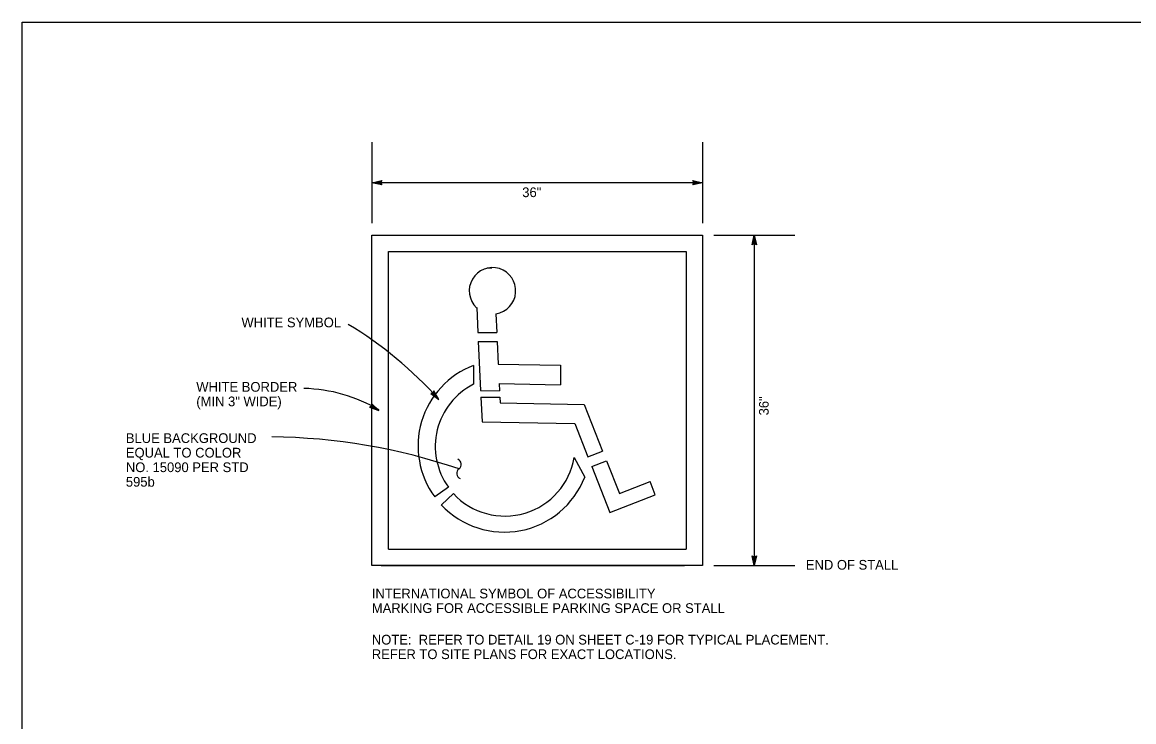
# Model space of a CAD drawing. Extents: x -121933 to -117742, y -103160 to -100084.
# Drawn here: x -119542 to -118856, y -101555 to -101122 of the extents above; entities that cross this region are included whole.
import ezdxf

# ---------------------------------------------------------------- set-up
doc = ezdxf.new("R2010")
doc.units = 0
for name, color, linetype in [('56 Stage 3 Anno', 7, 'Continuous'), ('57 Undefined', 7, 'Continuous'), ('60 Nongeo Data', 7, 'Continuous'), ('Default', 7, 'Continuous'), ('G-MARK', 7, 'Continuous'), ('G-TEXT', 7, 'Continuous'), ('Misc CnstDet(22)', 7, 'Continuous')]:
    doc.layers.add(name, color=color, linetype=linetype)

msp = doc.modelspace()

# ---------------------------------------------------------------- linework, layer by layer
at = {"layer": '56 Stage 3 Anno'}
for p, q in [((-119288.59, -101351.52), (-119290.12, -101351.82)), ((-119290.12, -101351.82), (-119290.12, -101351.82)), ((-119290.12, -101351.82), (-119285.13, -101355.41)), ((-119289.71, -101351.74), (-119286.05, -101354.38)), ((-119289.29, -101351.68), (-119286.97, -101353.34)), ((-119288.91, -101351.58), (-119287.89, -101352.31)), ((-119288.13, -101350.04), (-119288.59, -101351.52)), ((-119287.89, -101352.31), (-119288.49, -101351.23)), ((-119286.97, -101353.34), (-119288.38, -101350.82)), ((-119286.05, -101354.36), (-119288.24, -101350.46)), ((-119285.13, -101355.41), (-119288.13, -101350.04)), ((-119288.13, -101350.04), (-119288.13, -101350.04)), ((-119326.58, -101359.54), (-119327.95, -101360.28)), ((-119327.95, -101360.28), (-119327.95, -101360.28)), ((-119327.95, -101360.28), (-119322.1, -101362.18)), ((-119327.58, -101360.09), (-119323.29, -101361.48)), ((-119327.2, -101359.9), (-119324.48, -101360.78)), ((-119326.87, -101359.69), (-119325.67, -101360.07)), ((-119324.48, -101360.78), (-119326.6, -101358.8)), ((-119322.1, -101362.18), (-119326.59, -101357.98)), ((-119326.59, -101357.98), (-119326.59, -101357.98)), ((-119326.59, -101357.98), (-119326.58, -101359.54)), ((-119325.67, -101360.07), (-119326.58, -101359.23)), ((-119323.3, -101361.47), (-119326.57, -101358.41)), ((-119285.13, -101355.41), (-119285.13, -101355.41)), ((-119322.1, -101362.18), (-119322.1, -101362.18))]:
    msp.add_line(p, q, dxfattribs=at)
for centre, radius, start, end in [((-119466, -101516.62), 242.29, 41.71293, 58.95046), ((-119370.71, -101444.64), 96.01, 59.46122, 88.63427), ((-119391.38, -101745.24), 366.62, 71.09935, 89.52035), ((-119274.66, -101395.61), 3.45, 306.2821, 67.87649), ((-119270.58, -101401.16), 3.45, 126.2821, 247.87649)]:
    msp.add_arc(centre, radius, start, end, dxfattribs=at)
at = {"layer": '60 Nongeo Data'}
for p, q in [((-119326.38, -101458.12), (-119326.38, -101253.88)), ((-119320.75, -101253.88), (-119122.15, -101253.88)), ((-119122.15, -101253.88), (-119122.15, -101458.12)), ((-119316.26, -101264), (-119132.27, -101264)), ((-119316.26, -101447.99), (-119316.26, -101264)), ((-119132.27, -101264), (-119132.27, -101447.99)), ((-119255.18, -101274.13), (-119252.44, -101274.13)), ((-119261.74, -101298.77), (-119261.74, -101298.77)), ((-119261.7, -101298.63), (-119260.99, -101313.98)), ((-119249.8, -101302.46), (-119249.26, -101313.99)), ((-119260.99, -101313.98), (-119249.26, -101313.99)), ((-119260.73, -101319.68), (-119249.07, -101319.66)), ((-119260.73, -101319.68), (-119259.32, -101350.01)), ((-119249, -101319.67), (-119248.35, -101333.61)), ((-119263.63, -101334.43), (-119263.63, -101346.08)), ((-119248.35, -101333.61), (-119209.91, -101334.35)), ((-119209.91, -101334.35), (-119209.93, -101346.42)), ((-119247.79, -101345.69), (-119209.93, -101346.42)), ((-119247.79, -101345.69), (-119247.59, -101350.02)), ((-119259.33, -101350.01), (-119247.59, -101350.02)), ((-119259.14, -101354.08), (-119247.4, -101354.08)), ((-119259.13, -101354.08), (-119258.42, -101369.19)), ((-119247.4, -101354.08), (-119247.23, -101357.57)), ((-119247.23, -101357.57), (-119195.31, -101358.56)), ((-119195.31, -101358.56), (-119183.91, -101387.39)), ((-119258.42, -101369.19), (-119201.17, -101370.29)), ((-119201.17, -101370.29), (-119192.99, -101390.98)), ((-119192.99, -101390.98), (-119183.91, -101387.39)), ((-119201.43, -101391.3), (-119194.99, -101403.46)), ((-119190.64, -101396.92), (-119181.56, -101393.33)), ((-119181.56, -101393.33), (-119173.57, -101413.5)), ((-119190.64, -101396.92), (-119179.43, -101425.23)), ((-119173.57, -101413.5), (-119154.66, -101406.15)), ((-119151.46, -101414.36), (-119154.66, -101406.15)), ((-119279.18, -101409.61), (-119287.6, -101415.66)), ((-119276.09, -101413.64), (-119283.5, -101420.53)), ((-119179.43, -101425.23), (-119151.46, -101414.36)), ((-119316.26, -101447.99), (-119132.27, -101447.99)), ((-119320.75, -101458.12), (-119133.37, -101458.12))]:
    msp.add_line(p, q, dxfattribs=at)
msp.add_lwpolyline([(-119326.38, -101253.88), (-119122.15, -101253.88), (-119122.15, -101458.12), (-119326.38, -101458.12)], close=True, dxfattribs=at)
for centre, radius, start, end in [((-119251.95, -101288.28), 14.35, 278.63541, 226.98189), ((-119244.64, -101384.18), 53.27, 110.88771, 216.23262), ((-119244.64, -101384.18), 53.27, 110.88768, 216.23538), ((-119244.25, -101384.49), 43.02, 116.77664, 215.7522), ((-119244.27, -101384.04), 43.46, 222.92706, 350.38486), ((-119244.64, -101384.18), 53.27, 223.09166, 338.78141), ((-119244.64, -101384.18), 53.27, 338.78141, 338.80706)]:
    msp.add_arc(centre, radius, start, end, dxfattribs=at)
at = {"layer": 'Default'}
msp.add_lwpolyline([(-119542.38, -101122.36), (-117742.38, -101122.36), (-117742.38, -102572.36), (-119542.38, -102572.36)], close=True, dxfattribs=at)
at = {"layer": 'G-MARK'}
for p, q in [((-119122.15, -101221.54), (-119326.38, -101221.54)), ((-119090.24, -101253.88), (-119090.24, -101458.12))]:
    msp.add_line(p, q, dxfattribs=at)
at = {"layer": 'G-TEXT'}
for p, q in [((-119326.38, -101221.54), (-119320.38, -101220.21)), ((-119320.38, -101222.88), (-119326.38, -101221.54)), ((-119326.38, -101221.54), (-119326.38, -101221.54)), ((-119320.6, -101222.52), (-119325, -101221.54)), ((-119324.99, -101221.53), (-119320.62, -101220.57)), ((-119323.62, -101221.54), (-119320.8, -101220.91)), ((-119320.83, -101222.16), (-119323.62, -101221.54)), ((-119322.24, -101221.54), (-119321.03, -101221.27)), ((-119321.01, -101221.82), (-119322.24, -101221.54)), ((-119320.38, -101220.21), (-119321.18, -101221.54)), ((-119321.18, -101221.54), (-119320.38, -101222.88)), ((-119320.38, -101220.21), (-119320.38, -101220.21)), ((-119320.38, -101222.88), (-119320.38, -101222.88)), ((-119127.35, -101221.54), (-119128.15, -101220.2)), ((-119128.15, -101220.2), (-119128.15, -101220.2)), ((-119128.15, -101220.2), (-119122.15, -101221.54)), ((-119122.15, -101221.54), (-119128.15, -101222.87)), ((-119128.15, -101222.87), (-119127.35, -101221.54)), ((-119128.15, -101222.87), (-119128.15, -101222.87)), ((-119127.93, -101220.55), (-119123.53, -101221.54)), ((-119123.54, -101221.54), (-119127.91, -101222.51)), ((-119124.91, -101221.54), (-119127.73, -101222.16)), ((-119127.7, -101220.91), (-119124.91, -101221.54)), ((-119127.52, -101221.26), (-119126.29, -101221.53)), ((-119126.29, -101221.53), (-119127.5, -101221.8)), ((-119122.15, -101221.54), (-119122.15, -101221.54)), ((-119091.58, -101259.88), (-119090.24, -101253.88)), ((-119091.22, -101259.66), (-119090.24, -101255.26)), ((-119090.86, -101259.43), (-119090.24, -101256.64)), ((-119090.24, -101253.88), (-119090.24, -101253.88)), ((-119090.24, -101253.88), (-119088.91, -101259.88)), ((-119090.24, -101256.64), (-119089.61, -101259.47)), ((-119090.23, -101255.27), (-119089.27, -101259.64)), ((-119090.24, -101259.08), (-119091.58, -101259.88)), ((-119091.58, -101259.88), (-119091.58, -101259.88)), ((-119090.51, -101259.25), (-119090.24, -101258.02)), ((-119090.24, -101258.02), (-119089.97, -101259.23)), ((-119088.91, -101259.88), (-119090.24, -101259.08)), ((-119088.91, -101259.88), (-119088.91, -101259.88)), ((-119090.24, -101458.12), (-119091.57, -101452.12)), ((-119091.57, -101452.12), (-119091.57, -101452.12)), ((-119091.57, -101452.12), (-119090.24, -101452.92)), ((-119090.24, -101456.73), (-119091.21, -101452.35)), ((-119090.23, -101455.35), (-119090.86, -101452.53)), ((-119090.23, -101453.97), (-119090.5, -101452.76)), ((-119090.24, -101452.92), (-119088.9, -101452.12)), ((-119088.9, -101452.12), (-119090.24, -101458.12)), ((-119089.25, -101452.33), (-119090.24, -101456.74)), ((-119089.61, -101452.57), (-119090.23, -101455.35)), ((-119089.96, -101452.74), (-119090.23, -101453.97)), ((-119088.9, -101452.12), (-119088.9, -101452.12)), ((-119090.24, -101458.12), (-119090.24, -101458.12))]:
    msp.add_line(p, q, dxfattribs=at)
at = {"layer": 'Misc CnstDet(22)'}
for p, q in [((-119326.38, -101196.54), (-119326.38, -101246.54)), ((-119122.15, -101196.54), (-119122.15, -101246.54)), ((-119115.24, -101253.88), (-119065.24, -101253.88)), ((-119115.24, -101458.12), (-119065.24, -101458.12))]:
    msp.add_line(p, q, dxfattribs=at)

# ---------------------------------------------------------------- texts
at = {"layer": '57 Undefined'}
for s, p in [('WHITE SYMBOL', (-119406.98, -101310.85)), ('WHITE BORDER', (-119434.88, -101350.66)), ('(MIN 3" WIDE)', (-119434.88, -101359.66)), ('BLUE BACKGROUND', (-119478.37, -101382.34)), ('EQUAL TO COLOR', (-119478.37, -101391.34)), ('NO. 15090 PER STD', (-119478.37, -101400.34)), ('595b', (-119478.37, -101409.34)), ('END OF STALL', (-119058.4, -101460.62)), ('INTERNATIONAL SYMBOL OF ACCESSIBILITY', (-119326.47, -101478.37)), ('MARKING FOR ACCESSIBLE PARKING SPACE OR STALL', (-119326.47, -101487.37)), ('NOTE:  REFER TO DETAIL 19 ON SHEET C-19 FOR TYPICAL PLACEMENT.', (-119326.47, -101506.87)), ('REFER TO SITE PLANS FOR EXACT LOCATIONS.', (-119326.47, -101515.87))]:
    msp.add_text(s, height=6, dxfattribs=at).set_placement(p)
at = {"layer": 'Misc CnstDet(22)'}
for rotation, p in [(0.16798, (-119233.55, -101230.44)), (90.16798, (-119081.34, -101365.28))]:
    msp.add_text('36"', height=6, rotation=rotation, dxfattribs=at).set_placement(p)

doc.saveas('drawing.dxf')
